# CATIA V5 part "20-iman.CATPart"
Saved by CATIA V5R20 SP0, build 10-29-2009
Part number: 20-iman
Revision: ANY
Definition: UNKNOWN
Nomenclature: 20-iman
Source: Unknown
Bounding box of the stored display mesh (mm): x -6 to 6, y -5.85 to 5.85, z 0 to 2
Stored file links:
  C:\Users\Utente\Desktop\IO LAVORO\3D X SITO CF\CUMSA\3D files CX.013058\CX 013058\20-iman.CATPart
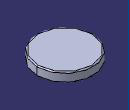
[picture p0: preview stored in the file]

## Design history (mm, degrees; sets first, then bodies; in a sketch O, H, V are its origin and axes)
Body1 "Redondeo1" (main body)
  Solid1: solid without history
